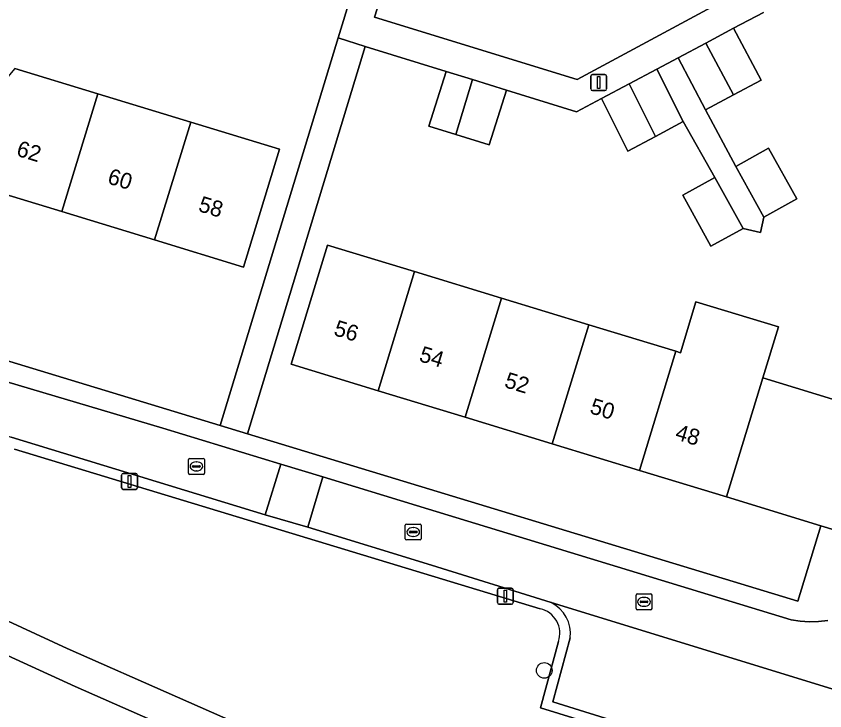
# Model space of a CAD drawing. Extents: x 160304 to 160955, y 383684 to 384161.
# Drawn here: x 160632.9 to 160683.6, y 383787 to 383830.6 of the extents above; entities that cross this region are included whole.
import ezdxf

# ---------------------------------------------------------------- set-up
doc = ezdxf.new("R2010")
doc.units = 0
for name, color, linetype in [('IMGEO_Boom', 7, 'Continuous'), ('IMGEO_Erf', 7, 'Continuous'), ('IMGEO_Groenvoorziening', 7, 'Continuous'), ('IMGEO_Kolk', 7, 'Continuous'), ('IMGEO_Lichtmast', 7, 'Continuous'), ('IMGEO_Pand', 7, 'Continuous'), ('IMGEO_Pand_nummerreeks', 7, 'Continuous'), ('IMGEO_Parkeervlak_open', 7, 'Continuous'), ('IMGEO_Rijbaan_lokaal_open', 7, 'Continuous'), ('IMGEO_Voetpad_halfverhard', 7, 'Continuous'), ('IMGEO_Voetpad_open', 7, 'Continuous')]:
    doc.layers.add(name, color=color, linetype=linetype)

msp = doc.modelspace()

# ---------------------------------------------------------------- linework, layer by layer
at = {"layer": 'IMGEO_Boom'}
msp.add_circle((160665.963, 383789.544), 0.489, dxfattribs=at)
at = {"layer": 'IMGEO_Erf'}
for points in [[(160630.04, 383809.657), (160645.643, 383804.913), (160653.036, 383829.224), (160654.59, 383834.285), (160649.562, 383835.841), (160648.5, 383832.466), (160646.621, 383833.04), (160644.721, 383833.621), (160645.787, 383837.008), (160641.818, 383838.236), (160639.864, 383841.919), (160636.708, 383840.209), (160635.753, 383841.969), (160634.828, 383843.676), (160638.017, 383845.404), (160636.28, 383848.678), (160636.837, 383850.561), (160633.474, 383851.564), (160634.058, 383853.448), (160634.642, 383855.331), (160629.872, 383856.923)], [(160679.704, 383830.827), (160677.836, 383829.832), (160679.559, 383826.569), (160677.824, 383825.649), (160676.07, 383824.719), (160677.965, 383821.158), (160680.029, 383822.302), (160681.787, 383819.128), (160679.723, 383817.984), (160679.521, 383817.014), (160678.422, 383817.269), (160676.4, 383816.158), (160674.642, 383819.357), (160676.664, 383820.468), (160674.661, 383823.984), (160672.931, 383823.05), (160671.201, 383822.117), (160669.545, 383825.42), (160667.989, 383824.592), (160663.59, 383825.955), (160662.511, 383822.526), (160660.408, 383823.173), (160658.735, 383823.687), (160659.817, 383827.123), (160654.739, 383828.696), (160647.349, 383804.394), (160681.863, 383793.899), (160683.302, 383798.622), (160677.387, 383800.427), (160671.927, 383802.092), (160666.466, 383803.759), (160661.006, 383805.425), (160655.545, 383807.091), (160650.085, 383808.757), (160652.364, 383816.227), (160657.825, 383814.561), (160663.285, 383812.895), (160668.746, 383811.229), (160674.206, 383809.564), (160674.497, 383809.475), (160675.472, 383812.672), (160680.64, 383811.096), (160679.665, 383807.898), (160685.059, 383806.252)], [(160632.764, 383827.308), (160637.98, 383825.716), (160643.802, 383823.94), (160649.366, 383822.242), (160647.111, 383814.853), (160641.516, 383816.56), (160635.725, 383818.327), (160627.376, 383820.875)]]:
    msp.add_lwpolyline(points, dxfattribs=at)
at = {"layer": 'IMGEO_Groenvoorziening'}
for points in [[(160512.051, 383860.483), (160527.152, 383851.99), (160555.752, 383830.697), (160558.345, 383828.766), (160565.781, 383823.661), (160582.534, 383812.776), (160600.019, 383802.155), (160610.062, 383796.203), (160622.299, 383789.443), (160640.34, 383780.06), (160649.742, 383775.545), (160664.695, 383768.884), (160685.542, 383758.679), (160684.972, 383756.649), (160697.446, 383751.712), (160700.343, 383760.526), (160696.112, 383762.451), (160684.565, 383767.367), (160636.545, 383788.535), (160627.316, 383792.767), (160623.864, 383794.407), (160613.532, 383800.088), (160603.749, 383806.669), (160564.231, 383837.826)], [(160592.198, 383828.52), (160589.078, 383820.852), (160606.303, 383807.27), (160613.979, 383802.041), (160620.758, 383798.197), (160628.361, 383794.476), (160636.045, 383790.923), (160677.55, 383772.608), (160678.007, 383772.445), (160678.477, 383772.323), (160678.955, 383772.244), (160679.439, 383772.208), (160679.924, 383772.215), (160680.407, 383772.266), (160680.883, 383772.359), (160681.349, 383772.495), (160681.801, 383772.671), (160682.235, 383772.888), (160682.649, 383773.142), (160683.038, 383773.432), (160683.399, 383773.756), (160683.73, 383774.111)], [(160665.712, 383793.418), (160632.749, 383803.427)], [(160685.879, 383780.972), (160665.729, 383787.196), (160666.847, 383791.357)]]:
    msp.add_lwpolyline(points, dxfattribs=at)
msp.add_arc((160665.359, 383791.881), 1.577, 340.6176, 77.0659, dxfattribs=at)
at = {"layer": 'IMGEO_Kolk'}
for p, q in [((160643.654, 383801.919), (160643.654, 383802.771)), ((160643.729, 383802.845), (160644.581, 383802.845)), ((160644.655, 383802.771), (160644.655, 383801.919)), ((160643.913, 383802.339), (160643.913, 383802.351)), ((160644.351, 383802.302), (160643.953, 383802.302)), ((160643.956, 383802.388), (160644.354, 383802.388)), ((160644.142, 383802.625), (160644.167, 383802.625)), ((160644.397, 383802.351), (160644.397, 383802.339)), ((160644.581, 383801.845), (160643.729, 383801.845)), ((160644.165, 383802.065), (160644.14, 383802.065)), ((160657.246, 383797.802), (160657.246, 383798.654)), ((160657.321, 383798.728), (160658.173, 383798.728)), ((160658.247, 383798.654), (160658.247, 383797.802)), ((160657.505, 383798.222), (160657.505, 383798.234)), ((160657.943, 383798.185), (160657.545, 383798.185)), ((160657.548, 383798.271), (160657.946, 383798.271)), ((160657.734, 383798.508), (160657.759, 383798.508)), ((160657.989, 383798.234), (160657.989, 383798.222)), ((160658.173, 383797.728), (160657.321, 383797.728)), ((160657.757, 383797.948), (160657.732, 383797.948)), ((160671.715, 383793.422), (160671.715, 383794.274)), ((160671.79, 383794.348), (160672.642, 383794.348)), ((160672.203, 383794.128), (160672.228, 383794.128)), ((160672.716, 383794.274), (160672.716, 383793.422)), ((160671.974, 383793.842), (160671.974, 383793.854)), ((160672.412, 383793.805), (160672.014, 383793.805)), ((160672.017, 383793.891), (160672.415, 383793.891)), ((160672.226, 383793.568), (160672.201, 383793.568)), ((160672.458, 383793.854), (160672.458, 383793.842)), ((160672.642, 383793.348), (160671.79, 383793.348))]:
    msp.add_line(p, q, dxfattribs=at)
for points in [[(160643.654, 383801.919), (160643.654, 383802.771)], [(160643.729, 383802.845), (160644.581, 383802.845)], [(160644.655, 383802.771), (160644.655, 383801.919)], [(160644.581, 383801.845), (160643.729, 383801.845)], [(160657.246, 383797.802), (160657.246, 383798.654)], [(160657.321, 383798.728), (160658.173, 383798.728)], [(160658.247, 383798.654), (160658.247, 383797.802)], [(160658.173, 383797.728), (160657.321, 383797.728)], [(160671.715, 383793.422), (160671.715, 383794.274)], [(160671.79, 383794.348), (160672.642, 383794.348)], [(160672.716, 383794.274), (160672.716, 383793.422)], [(160672.642, 383793.348), (160671.79, 383793.348)]]:
    msp.add_lwpolyline(points, dxfattribs=at)
for centre, radius, start, end in [((160643.731, 383802.769), 0.0765, 91.552, 178.448), ((160643.731, 383802.769), 0.0765, 91.552, 178.448), ((160644.579, 383802.769), 0.0765, 1.552, 88.448), ((160644.579, 383802.769), 0.0765, 1.552, 88.448), ((160643.953, 383802.348), 0.0403, 85.8775, 175.7526), ((160643.95, 383802.338), 0.0366, 178.938, 274.7102), ((160644.354, 383802.345), 0.043, 264.8664, 352.4533), ((160644.358, 383802.35), 0.0386, 1.7309, 96.639), ((160643.731, 383801.921), 0.0765, 181.552, 268.448), ((160643.731, 383801.921), 0.0765, 181.552, 268.448), ((160644.579, 383801.921), 0.0765, 271.552, 358.448), ((160644.579, 383801.921), 0.0765, 271.552, 358.448), ((160657.323, 383798.652), 0.0765, 91.552, 178.448), ((160657.323, 383798.652), 0.0765, 91.552, 178.448), ((160658.171, 383798.652), 0.0765, 1.552, 88.448), ((160658.171, 383798.652), 0.0765, 1.552, 88.448), ((160657.545, 383798.231), 0.0403, 85.8775, 175.7526), ((160657.542, 383798.221), 0.0366, 178.938, 274.7102), ((160657.946, 383798.228), 0.043, 264.8664, 352.4533), ((160657.95, 383798.233), 0.0386, 1.7309, 96.639), ((160657.323, 383797.804), 0.0765, 181.552, 268.448), ((160657.323, 383797.804), 0.0765, 181.552, 268.448), ((160658.171, 383797.804), 0.0765, 271.552, 358.448), ((160658.171, 383797.804), 0.0765, 271.552, 358.448), ((160671.792, 383794.272), 0.0765, 91.552, 178.448), ((160671.792, 383794.272), 0.0765, 91.552, 178.448), ((160672.64, 383794.272), 0.0765, 1.552, 88.448), ((160672.64, 383794.272), 0.0765, 1.552, 88.448), ((160672.014, 383793.851), 0.0403, 85.8775, 175.7526), ((160672.011, 383793.841), 0.0366, 178.938, 274.7102), ((160672.415, 383793.848), 0.043, 264.8664, 352.4533), ((160672.419, 383793.853), 0.0386, 1.7309, 96.639), ((160671.792, 383793.424), 0.0765, 181.552, 268.448), ((160671.792, 383793.424), 0.0765, 181.552, 268.448), ((160672.64, 383793.424), 0.0765, 271.552, 358.448), ((160672.64, 383793.424), 0.0765, 271.552, 358.448)]:
    msp.add_arc(centre, radius, start, end, dxfattribs=at)
for centre, major_axis, ratio, start_param, end_param in [((160644.141, 383802.345), (-0.387, 0.002), 0.722429, 4.712389, 7.853982), ((160644.166, 383802.345), (-0.39, 0.002), 0.717154, 1.570796, 4.712389), ((160657.733, 383798.228), (-0.387, 0.002), 0.722429, 4.712389, 7.853982), ((160657.758, 383798.228), (-0.39, 0.002), 0.717154, 1.570796, 4.712389), ((160672.202, 383793.848), (-0.387, 0.002), 0.722429, 4.712389, 7.853982), ((160672.227, 383793.848), (-0.39, 0.002), 0.717154, 1.570796, 4.712389)]:
    msp.add_ellipse(centre, major_axis=major_axis, ratio=ratio, start_param=start_param, end_param=end_param, dxfattribs=at)
at = {"layer": 'IMGEO_Lichtmast'}
for p, q in [((160668.877, 383826.027), (160668.877, 383826.827)), ((160668.877, 383826.827), (160668.877, 383826.027)), ((160668.977, 383826.927), (160669.767, 383826.927)), ((160669.767, 383826.927), (160668.977, 383826.927)), ((160669.867, 383826.827), (160669.867, 383826.027)), ((160669.867, 383826.027), (160669.867, 383826.827)), ((160669.767, 383825.927), (160668.977, 383825.927)), ((160668.977, 383825.927), (160669.767, 383825.927)), ((160639.463, 383800.998), (160639.463, 383801.798)), ((160639.463, 383801.798), (160639.463, 383800.998)), ((160639.563, 383801.898), (160640.353, 383801.898)), ((160640.353, 383801.898), (160639.563, 383801.898)), ((160640.453, 383801.798), (160640.453, 383800.998)), ((160640.453, 383800.998), (160640.453, 383801.798)), ((160640.353, 383800.898), (160639.563, 383800.898)), ((160639.563, 383800.898), (160640.353, 383800.898)), ((160663.023, 383793.798), (160663.023, 383794.598)), ((160663.023, 383794.598), (160663.023, 383793.798)), ((160663.123, 383794.698), (160663.913, 383794.698)), ((160663.913, 383794.698), (160663.123, 383794.698)), ((160664.013, 383794.598), (160664.013, 383793.798)), ((160664.013, 383793.798), (160664.013, 383794.598)), ((160663.913, 383793.698), (160663.123, 383793.698)), ((160663.123, 383793.698), (160663.913, 383793.698))]:
    msp.add_line(p, q, dxfattribs=at)
for points in [[(160669.297, 383826.802), (160669.447, 383826.802), (160669.447, 383826.052), (160669.297, 383826.052), (160669.297, 383826.802)], [(160639.883, 383801.773), (160640.033, 383801.773), (160640.033, 383801.023), (160639.883, 383801.023), (160639.883, 383801.773)], [(160663.443, 383794.573), (160663.593, 383794.573), (160663.593, 383793.823), (160663.443, 383793.823), (160663.443, 383794.573)]]:
    msp.add_lwpolyline(points, dxfattribs=at)
for centre, start, end in [((160668.977, 383826.827), 90, 180), ((160668.977, 383826.827), 90, 180), ((160669.767, 383826.827), 0, 90), ((160669.767, 383826.827), 360, 90), ((160668.977, 383826.027), 180, 270), ((160668.977, 383826.027), 180, 270), ((160669.767, 383826.027), 270, 0), ((160669.767, 383826.027), 270, 0), ((160639.563, 383801.798), 90, 180), ((160639.563, 383801.798), 90, 180), ((160640.353, 383801.798), 0, 90), ((160640.353, 383801.798), 360, 90), ((160639.563, 383800.998), 180, 270), ((160639.563, 383800.998), 180, 270), ((160640.353, 383800.998), 270, 0), ((160640.353, 383800.998), 270, 0), ((160663.123, 383794.598), 90, 180), ((160663.123, 383794.598), 90, 180), ((160663.913, 383794.598), 0, 90), ((160663.913, 383794.598), 360, 90), ((160663.123, 383793.798), 180, 270), ((160663.123, 383793.798), 180, 270), ((160663.913, 383793.798), 270, 0), ((160663.913, 383793.798), 270, 0)]:
    msp.add_arc(centre, 0.1, start, end, dxfattribs=at)
at = {"layer": 'IMGEO_Pand'}
for points in [[(160676.091, 383828.904), (160677.824, 383825.649), (160679.559, 383826.569), (160677.836, 383829.832)], [(160676.091, 383828.904), (160674.349, 383827.977), (160676.07, 383824.719), (160677.824, 383825.649)], [(160637.98, 383825.716), (160632.764, 383827.308), (160627.376, 383820.875), (160635.725, 383818.327)], [(160660.408, 383823.173), (160661.458, 383826.615), (160659.817, 383827.123), (160658.735, 383823.687)], [(160671.28, 383826.344), (160672.931, 383823.05), (160674.661, 383823.984), (160673.015, 383827.267)], [(160660.408, 383823.173), (160662.511, 383822.526), (160663.59, 383825.955), (160661.458, 383826.615)], [(160671.28, 383826.344), (160669.545, 383825.42), (160671.201, 383822.117), (160672.931, 383823.05)], [(160641.516, 383816.56), (160643.802, 383823.94), (160637.98, 383825.716), (160635.725, 383818.327)], [(160641.516, 383816.56), (160647.111, 383814.853), (160649.366, 383822.242), (160643.802, 383823.94)], [(160677.965, 383821.158), (160679.723, 383817.984), (160681.787, 383819.128), (160680.029, 383822.302)], [(160676.664, 383820.468), (160674.642, 383819.357), (160676.4, 383816.158), (160678.422, 383817.269)], [(160657.825, 383814.561), (160652.364, 383816.227), (160650.085, 383808.757), (160655.545, 383807.091)], [(160663.285, 383812.895), (160657.825, 383814.561), (160655.545, 383807.091), (160661.006, 383805.425)], [(160668.746, 383811.229), (160663.285, 383812.895), (160661.006, 383805.425), (160666.466, 383803.759)], [(160679.665, 383807.898), (160680.64, 383811.096), (160675.472, 383812.672), (160674.497, 383809.475), (160674.206, 383809.564), (160671.927, 383802.092), (160677.387, 383800.427)], [(160694.073, 383809.418), (160686.712, 383811.669), (160685.059, 383806.252), (160679.665, 383807.898), (160677.387, 383800.427), (160683.302, 383798.622), (160687.175, 383797.44), (160688.311, 383798.045), (160689.891, 383798.887), (160691.047, 383799.502), (160692.164, 383803.164)], [(160674.206, 383809.564), (160668.746, 383811.229), (160666.466, 383803.759), (160671.927, 383802.092)]]:
    msp.add_lwpolyline(points, close=True, dxfattribs=at)
at = {"layer": 'IMGEO_Parkeervlak_open'}
for points in [[(160663.159, 383848.277), (160663.061, 383848.16), (160672.095, 383831.365), (160657.06, 383835.957), (160656.978, 383835.701), (160655.326, 383830.534), (160668.018, 383826.622), (160677.266, 383831.583), (160667.453, 383849.822), (160664.855, 383848.464)], [(160687.252, 383787.394), (160666.388, 383793.796)], [(160667.595, 383791.594), (160666.5, 383787.57), (160685.644, 383781.602), (160687.061, 383786.904)]]:
    msp.add_lwpolyline(points, dxfattribs=at)
msp.add_arc((160665.42, 383791.834), 2.188, 353.7142, 63.7435, dxfattribs=at)
at = {"layer": 'IMGEO_Rijbaan_lokaal_open'}
for points in [[(160627.373, 383805.768), (160632.544, 383804.181), (160639.862, 383801.938), (160648.47, 383799.311), (160649.444, 383802.481), (160642.055, 383804.752), (160629.871, 383808.362), (160629.33, 383808.487), (160628.728, 383808.68), (160628.145, 383808.926), (160627.587, 383809.224), (160627.058, 383809.57), (160626.562, 383809.961), (160626.103, 383810.396), (160625.684, 383810.87), (160625.31, 383811.379), (160624.982, 383811.92), (160616.002, 383828.924), (160613.121, 383827.402), (160620.166, 383814.09), (160622.284, 383810.088)], [(160683.73, 383792.686), (160683.158, 383792.617), (160682.583, 383792.6), (160682.009, 383792.634), (160681.44, 383792.719), (160657.945, 383799.886), (160652.079, 383801.685), (160651.135, 383798.527), (160658.883, 383796.149), (160666.388, 383793.796), (160687.252, 383787.394)]]:
    msp.add_lwpolyline(points, dxfattribs=at)
msp.add_lwpolyline([(160649.444, 383802.481), (160648.47, 383799.311), (160651.135, 383798.527), (160652.079, 383801.685)], close=True, dxfattribs=at)
at = {"layer": 'IMGEO_Voetpad_halfverhard'}
for points in [[(160587.546, 383868.946), (160567.255, 383845.98), (160567.181, 383845.905), (160566.724, 383845.485), (160566.231, 383845.107), (160565.706, 383844.775), (160565.154, 383844.491), (160564.578, 383844.257), (160563.984, 383844.076), (160563.376, 383843.949), (160564.231, 383837.826), (160603.749, 383806.669), (160613.532, 383800.088), (160623.864, 383794.407), (160627.316, 383792.767), (160636.545, 383788.535), (160684.565, 383767.367)], [(160683.73, 383774.111), (160683.399, 383773.756), (160683.038, 383773.432), (160682.649, 383773.142), (160682.235, 383772.888), (160681.801, 383772.671), (160681.349, 383772.495), (160680.883, 383772.359), (160680.407, 383772.266), (160679.924, 383772.215), (160679.439, 383772.208), (160678.955, 383772.244), (160678.477, 383772.323), (160678.007, 383772.445), (160677.55, 383772.608), (160636.045, 383790.923), (160628.361, 383794.476), (160620.758, 383798.197), (160613.979, 383802.041), (160606.303, 383807.27), (160589.078, 383820.852)]]:
    msp.add_lwpolyline(points, dxfattribs=at)
at = {"layer": 'IMGEO_Voetpad_open'}
for points in [[(160687.175, 383797.44), (160683.302, 383798.622), (160681.863, 383793.899), (160647.349, 383804.394), (160645.643, 383804.913), (160630.04, 383809.657), (160629.92, 383809.684), (160629.419, 383809.824), (160628.933, 383810.009), (160628.465, 383810.236), (160628.02, 383810.504), (160627.6, 383810.811), (160627.209, 383811.154), (160626.85, 383811.531), (160626.527, 383811.938), (160626.241, 383812.373), (160608.312, 383846.103), (160602.222, 383857.561), (160606.586, 383859.913), (160605.024, 383862.845)], [(160664.319, 383848.183), (160664.855, 383848.464), (160667.453, 383849.822), (160677.266, 383831.583), (160668.018, 383826.622), (160655.326, 383830.534), (160656.978, 383835.701), (160657.06, 383835.957), (160658.353, 383839.999)], [(160654.59, 383834.285), (160653.036, 383829.224), (160654.739, 383828.696), (160659.817, 383827.123), (160661.458, 383826.615), (160663.59, 383825.955), (160667.989, 383824.592), (160669.545, 383825.42), (160671.28, 383826.344), (160673.015, 383827.267), (160674.349, 383827.977), (160676.091, 383828.904), (160677.836, 383829.832), (160679.704, 383830.827)], [(160629.871, 383808.362), (160642.055, 383804.752), (160649.444, 383802.481), (160652.079, 383801.685), (160657.945, 383799.886), (160681.44, 383792.719), (160682.009, 383792.634), (160682.583, 383792.6), (160683.158, 383792.617), (160683.73, 383792.686)], [(160651.135, 383798.527), (160648.47, 383799.311), (160639.862, 383801.938), (160632.544, 383804.181)], [(160632.749, 383803.427), (160665.712, 383793.418)], [(160666.388, 383793.796), (160658.883, 383796.149), (160651.135, 383798.527)], [(160687.061, 383786.904), (160685.644, 383781.602), (160666.5, 383787.57), (160667.595, 383791.594)], [(160666.847, 383791.357), (160665.729, 383787.196), (160685.879, 383780.972), (160686.088, 383780.908), (160687.716, 383786.947)]]:
    msp.add_lwpolyline(points, dxfattribs=at)
for points in [[(160654.739, 383828.696), (160653.036, 383829.224), (160645.643, 383804.913), (160647.349, 383804.394)], [(160676.07, 383824.719), (160674.349, 383827.977), (160673.015, 383827.267), (160674.661, 383823.984), (160676.664, 383820.468), (160678.422, 383817.269), (160679.521, 383817.014), (160679.723, 383817.984), (160677.965, 383821.158)]]:
    msp.add_lwpolyline(points, close=True, dxfattribs=at)
for centre, radius, start, end in [((160665.42, 383791.834), 2.188, 353.7142, 63.7435), ((160665.359, 383791.881), 1.577, 340.6176, 77.0659)]:
    msp.add_arc(centre, radius, start, end, dxfattribs=at)

# ---------------------------------------------------------------- texts
at = {"layer": 'IMGEO_Pand_nummerreeks'}
for s, rotation, p in [('62', 343.0275, (160632.808, 383821.852)), ('60', 343.0324, (160638.519, 383820.109)), ('58', 343.0324, (160644.212, 383818.372)), ('56', 343.0347, (160652.706, 383810.592)), ('54', 343.0347, (160658.057, 383808.96)), ('52', 343.0347, (160663.404, 383807.328)), ('50', 343.0347, (160668.76, 383805.694)), ('48', 343.0347, (160674.111, 383804.061))]:
    msp.add_text(s, height=1, rotation=rotation, dxfattribs=at).set_placement(p)

doc.saveas('drawing.dxf')
